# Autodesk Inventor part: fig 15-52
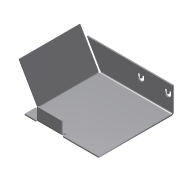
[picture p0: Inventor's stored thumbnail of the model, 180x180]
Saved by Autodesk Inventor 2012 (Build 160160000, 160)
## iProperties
Shininess: 77.0
Angle Display Precision: 2
Document Length Units: 11269
Document Angle Units: 11279
Document Time Units: 11290
Document Mass Units: 11283
Document Length Units Precision: 3
Document Angle Units Precision: 2
Created: 2002-04
Part Number: fig 15-52
Document SubType Name: Sheet Metal
Density: 1 g/cm^3
Sheet Metal Rule: Default
Material: Default
Density: 0.0
Volumn: 0.0
Area: 0.0
PropertySet Name: Model Information
Control State: 0
Master: False
Checked Out: False
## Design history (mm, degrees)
node "Face1"
  sketch "Sketch1"
    geometry: L1 (12.647, 25.882)-(12.647, -14.118); L2 (12.647, -14.118)-(-17.353, -14.118); L3 (-17.353, -14.118)-(-17.353, 15.882); L4 (-17.353, 15.882)-(-2.353, 15.882); L5 (-2.353, 15.882)-(-2.353, 25.882); L6 (-2.353, 25.882)-(12.647, 25.882); 1 further point
    constraints: 12 end point, 4 parallel, 1 perpendicular
    dimensions: "d5" = 30 distance of L2.end L3.end; "d6" = 10 distance of L4.end L5.end; "d7" = 15 distance of L3.end L4.end; "d25" = 15 distance of L5.end L1.start
sketch "Sketch3"
  geometry: L1 (10, -15)-(10, 0)
  constraints: 2 end point
feature "Fold3" sketch "Sketch3" dims "d26" = 0.5 (= BendRadius), "d27" = 90 deg, "d28" = 0.5 (= BendRadius), "d96" = 0.5 (= BendReliefWidth), "d97" = 0.25 (= BendReliefDepth), "d98" = 1 (= MinimumRemnant), "SeamGap" = 0.01, "Thickness" = 0.5
node "Flange2"
sketch "Sketch6"
  geometry: L1 (-6.914, 3.413)-(-5.843, 3.413); L2 (-5.843, 0.624)-(-6.914, 0.624); L3 (-6.914, 2.432)-(-5.843, 2.432); L4 (-5.843, 1.605)-(-6.914, 1.605); L5 (-6.914, 0.624)-(-6.914, 1.605); L6 (-6.914, 2.432)-(-6.914, 3.413); L7 (-6.914, 12.568)-(-6.914, 11.587); L8 (-6.914, 14.376)-(-6.914, 13.395); L9 (-6.914, 11.587)-(-5.843, 11.587); L10 (-5.843, 14.376)-(-6.914, 14.376); L11 (-6.914, 12.568)-(-5.843, 12.568); L12 (-5.843, 13.395)-(-6.914, 13.395); A1 r 1.394 centre (-5.843, 2.018) between (-5.843, 0.624) and (-5.843, 3.413); A2 r 0.413 centre (-5.843, 2.018) between (-5.843, 1.605) and (-5.843, 2.432); A3 r 1.394 centre (-5.843, 12.982) between (-5.843, 11.587) and (-5.843, 14.376); A4 r 0.413 centre (-5.843, 12.982) between (-5.843, 12.568) and (-5.843, 13.395)
  constraints: 24 end point, 8 point on circle, 4 centre point, 3 equal length, 1 perpendicular
cut "Cut1" sketch "Sketch6" dims "d49" = 0.5 (= Thickness), "d50" = 0
node "Flange3"
feature "Corner3" dims "d107" = 2 (= CornerReliefSize), "d108" = 0.5 (= BendRadius), "d109" = 0.5 (= GapSize), "d110" = 0, "d111" = 10, "Thickness" = 0.5
body "Solid1"
face "Plate1" dims "Thickness" = 0.5
sketch "Sketch5"
  geometry: L1 (20, 0)-(5, 0); L2 (5, 0)-(5, 15); L3 (5, 15)-(20, 15); L4 (20, 15)-(20, 0)
  constraints: 8 end point
face "Plate6" dims "d35" = 10, "d36" = 5, "d38" = 15, "d39" = 60 deg, "d40" = 0.5 (= BendRadius), "Thickness" = 0.5, "MinimumRemnant" = 1 (= 2 x Thickness), "BendReliefWidth" = 0.5 (= Thickness)
bend "Bend5" dims "d38" = 15, "d39" = 60 deg, "d40" = 0.5 (= BendRadius), "d99" = 0.5 (= BendReliefWidth), "d100" = 0.25 (= BendReliefDepth), "d101" = 1 (= MinimumRemnant), "SeamGap" = 0.01, "Thickness" = 0.5, "MinimumRemnant" = 1 (= 2 x Thickness), "BendReliefWidth" = 0.5 (= Thickness), "TransitionRadius" = 0.5 (= BendRadius)
sketch "Sketch7"
  geometry: L1 (25, 0)-(15, 0); L2 (15, 0)-(15, 5); L3 (15, 5)-(25, 5); L4 (25, 5)-(25, 0)
  constraints: 8 end point
face "Plate7" dims "d57" = 5, "d58" = 10, "d60" = 5, "d61" = 90 deg, "d62" = 0.5 (= BendRadius), "Thickness" = 0.5, "MinimumRemnant" = 1 (= 2 x Thickness), "BendReliefWidth" = 0.5 (= Thickness)
bend "Bend7" dims "d59" = 0.5 (= BendRadius), "d60" = 5, "d61" = 90 deg, "d62" = 0.5 (= BendRadius), "d102" = 0.5 (= BendReliefWidth), "d103" = 0.25 (= BendReliefDepth), "d104" = 1 (= MinimumRemnant), "SeamGap" = 0.01, "Thickness" = 0.5, "MinimumRemnant" = 1 (= 2 x Thickness), "BendReliefWidth" = 0.5 (= Thickness)
other parameters: "BendRadius" = 0.5 (= Thickness), "BendReliefDepth" = 0.25 (= 0.5 x Thickness), "CornerReliefSize" = 2 (= 4 x Thickness), "d0" = 0.5 (= BendRadius), "d13" = 0.5 (= BendRadius), "d31" = 0.5 (= BendRadius), "d37" = 0.5 (= BendRadius), "JacobiRadiusSize" = 0.5 (= Thickness), "GapSize" = 0.5 (= Thickness)
